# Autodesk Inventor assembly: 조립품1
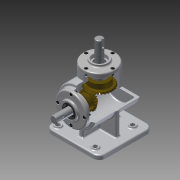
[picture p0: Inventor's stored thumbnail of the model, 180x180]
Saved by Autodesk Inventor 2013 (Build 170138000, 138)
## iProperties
Created: 2015-07
Part Number: 조립품1
Document SubType Name: Assembly
Designer: Administrator
Author: Administrator
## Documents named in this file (14)
- C:\Users\Administrator\Desktop\450706V1006\조립품1.iam
- C:\Users\Administrator\Desktop\450706V1006\본체.ipt
- C:\Users\Administrator\Desktop\450706V1006\메인 축.ipt
- 메인 축.ipt
- C:\Users\Administrator\Desktop\450706V1006\베어링 6203.ipt
- C:\Users\Administrator\Desktop\450706V1006\커버.ipt
- C:\Users\Administrator\Desktop\450706V1006\오일실.ipt
- C:\Users\Administrator\Desktop\450706V1006\M4.ipt
- C:\Users\Administrator\Desktop\450706V1006\메인 베벨기어.ipt
- C:\Users\Administrator\Desktop\450706V1006\키 4x4.ipt
- C:\Users\Administrator\Desktop\450706V1006\서브 베벨기어.ipt
- C:\Users\Administrator\Desktop\450706V1006\서브 축.ipt
- 서브 축.ipt
- C:\Users\Administrator\Desktop\450706V1006\키 5x5.ipt
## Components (8 placed, 1 different names)
1. M4:1
2. M4:2
3. M4:3
4. M4:4
5. M4:5
6. M4:6
7. M4:7
8. M4:8
